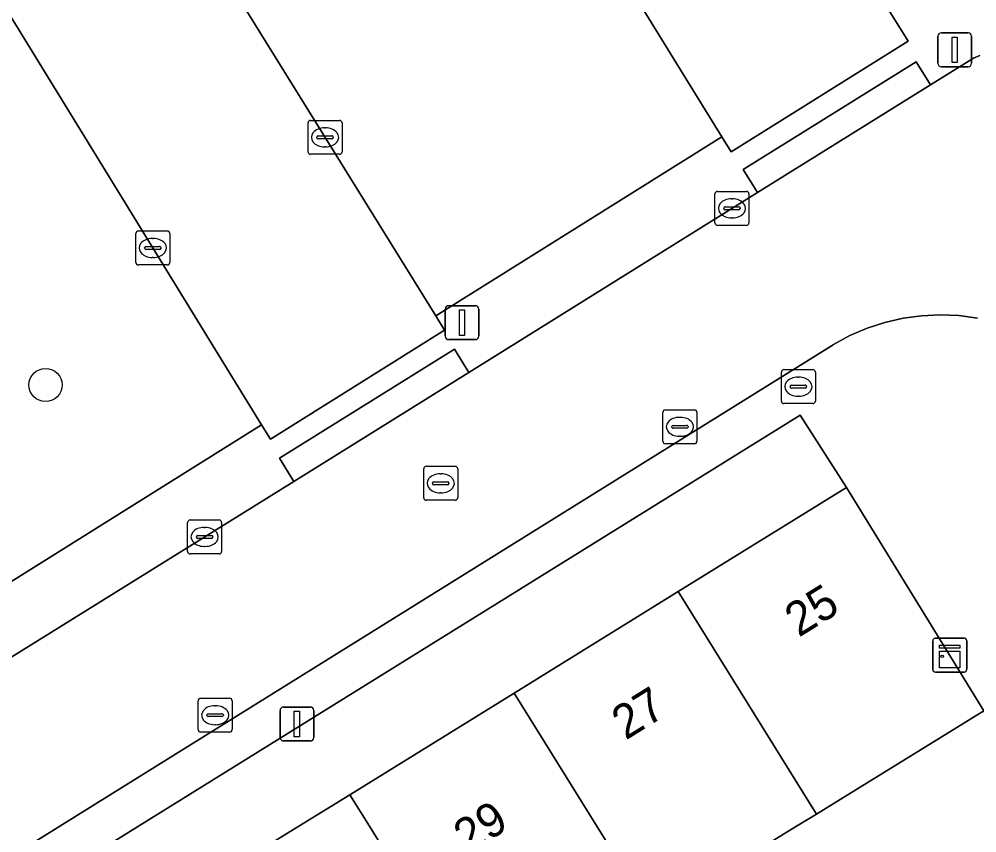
# Model space of a CAD drawing. Extents: x 160304 to 160955, y 383684 to 384161.
# Drawn here: x 160703.42 to 160731.63, y 383999.81 to 384023.78 of the extents above; entities that cross this region are included whole.
import ezdxf

# ---------------------------------------------------------------- set-up
doc = ezdxf.new("R2010")
doc.units = 0
for name, color, linetype in [('IMGEO_Boom', 7, 'Continuous'), ('IMGEO_Brandkraan', 7, 'Continuous'), ('IMGEO_Erf', 7, 'Continuous'), ('IMGEO_Kast', 7, 'Continuous'), ('IMGEO_Kolk', 7, 'Continuous'), ('IMGEO_Lichtmast', 7, 'Continuous'), ('IMGEO_Pand', 7, 'Continuous'), ('IMGEO_Pand_nummerreeks', 7, 'Continuous'), ('IMGEO_Parkeervlak_open', 7, 'Continuous'), ('IMGEO_Rijbaan_lokaal_open', 7, 'Continuous'), ('IMGEO_Rioolput', 7, 'Continuous'), ('IMGEO_Voetpad_open', 7, 'Continuous')]:
    doc.layers.add(name, color=color, linetype=linetype)

msp = doc.modelspace()

# ---------------------------------------------------------------- linework, layer by layer
at = {"layer": 'IMGEO_Boom'}
msp.add_circle((160704.196, 384013.001), 0.489, dxfattribs=at)
at = {"layer": 'IMGEO_Brandkraan'}
for p, q in [((160725.946, 384013.453), (160726.798, 384013.453)), ((160725.871, 384012.527), (160725.871, 384013.379)), ((160726.359, 384013.233), (160726.384, 384013.233)), ((160726.872, 384013.379), (160726.872, 384012.527)), ((160726.13, 384012.947), (160726.13, 384012.959)), ((160726.568, 384012.91), (160726.17, 384012.91)), ((160726.173, 384012.996), (160726.571, 384012.996)), ((160726.614, 384012.959), (160726.614, 384012.947)), ((160726.382, 384012.673), (160726.357, 384012.673)), ((160726.798, 384012.453), (160725.946, 384012.453))]:
    msp.add_line(p, q, dxfattribs=at)
for points in [[(160725.946, 384013.453), (160726.798, 384013.453)], [(160725.871, 384012.527), (160725.871, 384013.379)], [(160726.872, 384013.379), (160726.872, 384012.527)], [(160726.798, 384012.453), (160725.946, 384012.453)]]:
    msp.add_lwpolyline(points, dxfattribs=at)
for centre, radius, start, end in [((160725.948, 384013.377), 0.0765, 91.552, 178.448), ((160725.948, 384013.377), 0.0765, 91.552, 178.448), ((160726.796, 384013.377), 0.0765, 1.552, 88.448), ((160726.796, 384013.377), 0.0765, 1.552, 88.448), ((160726.17, 384012.956), 0.0403, 85.8775, 175.7526), ((160726.167, 384012.946), 0.0366, 178.938, 274.7102), ((160726.571, 384012.953), 0.043, 264.8664, 352.4533), ((160726.575, 384012.958), 0.0386, 1.7309, 96.639), ((160725.948, 384012.529), 0.0765, 181.552, 268.448), ((160725.948, 384012.529), 0.0765, 181.552, 268.448), ((160726.796, 384012.529), 0.0765, 271.552, 358.448), ((160726.796, 384012.529), 0.0765, 271.552, 358.448)]:
    msp.add_arc(centre, radius, start, end, dxfattribs=at)
for centre, major_axis, ratio, start_param, end_param in [((160726.358, 384012.953), (-0.387, 0.002), 0.722429, 4.712389, 7.853982), ((160726.383, 384012.953), (-0.39, 0.002), 0.717154, 1.570796, 4.712389)]:
    msp.add_ellipse(centre, major_axis=major_axis, ratio=ratio, start_param=start_param, end_param=end_param, dxfattribs=at)
at = {"layer": 'IMGEO_Erf'}
for points in [[(160708.32, 383997.939), (160711.652, 384000), (160713.157, 384000.931), (160717.995, 384003.923), (160722.832, 384006.915), (160727.787, 384009.979), (160726.422, 384012.115), (160706.936, 384000), (160687.05, 383987.636), (160676.351, 384000), (160656.955, 384022.413), (160655.424, 384021.087), (160659.239, 384016.681), (160662.975, 384012.366), (160666.712, 384008.05), (160670.447, 384003.736), (160673.681, 384000), (160674.183, 383999.42)], [(160736.358, 383996.235), (160733.983, 384000), (160731.839, 384003.398), (160727.6, 384000.788), (160726.904, 384000.36), (160726.32, 384000), (160722.061, 383997.377)]]:
    msp.add_lwpolyline(points, dxfattribs=at)
at = {"layer": 'IMGEO_Kast'}
for p, q in [((160730.404, 384005.542), (160731.245, 384005.542)), ((160731.245, 384005.542), (160730.404, 384005.542)), ((160730.329, 384004.617), (160730.329, 384005.458)), ((160730.329, 384005.458), (160730.329, 384004.617)), ((160731.329, 384005.467), (160731.329, 384004.626)), ((160731.329, 384004.626), (160731.329, 384005.467)), ((160731.254, 384004.542), (160730.413, 384004.542)), ((160730.413, 384004.542), (160731.254, 384004.542))]:
    msp.add_line(p, q, dxfattribs=at)
for points in [[(160730.524, 384005.332), (160731.124, 384005.332), (160731.124, 384005.247), (160730.524, 384005.247), (160730.524, 384005.332)], [(160730.524, 384005.157), (160731.124, 384005.157), (160731.124, 384004.668), (160730.524, 384004.668), (160730.524, 384005.157)]]:
    msp.add_lwpolyline(points, dxfattribs=at)
msp.add_circle((160730.608, 384005.006), 0.0377, dxfattribs=at)
for centre, start, end in [((160730.407, 384005.464), 92.4484, 184.2845), ((160730.407, 384005.464), 92.4484, 184.2845), ((160731.251, 384005.464), 2.4484, 94.2845), ((160731.251, 384005.464), 2.4484, 94.2845), ((160730.407, 384004.62), 182.4484, 274.2845), ((160730.407, 384004.62), 182.4484, 274.2845), ((160731.251, 384004.62), 272.4484, 4.2845), ((160731.251, 384004.62), 272.4484, 4.2845)]:
    msp.add_arc(centre, 0.0779, start, end, dxfattribs=at)
at = {"layer": 'IMGEO_Kolk'}
for p, q in [((160711.928, 384019.87), (160711.928, 384020.722)), ((160712.003, 384020.796), (160712.855, 384020.796)), ((160712.929, 384020.722), (160712.929, 384019.87)), ((160712.416, 384020.576), (160712.441, 384020.576)), ((160712.187, 384020.29), (160712.187, 384020.302)), ((160712.625, 384020.253), (160712.227, 384020.253)), ((160712.23, 384020.339), (160712.628, 384020.339)), ((160712.671, 384020.302), (160712.671, 384020.29)), ((160712.439, 384020.016), (160712.414, 384020.016)), ((160712.855, 384019.796), (160712.003, 384019.796)), ((160723.914, 384017.777), (160723.914, 384018.629)), ((160723.989, 384018.703), (160724.841, 384018.703)), ((160724.402, 384018.483), (160724.427, 384018.483)), ((160724.915, 384018.629), (160724.915, 384017.777)), ((160724.173, 384018.197), (160724.173, 384018.209)), ((160724.216, 384018.246), (160724.614, 384018.246)), ((160724.657, 384018.209), (160724.657, 384018.197)), ((160724.611, 384018.16), (160724.213, 384018.16)), ((160724.425, 384017.923), (160724.4, 384017.923)), ((160724.841, 384017.703), (160723.989, 384017.703)), ((160706.854, 384016.612), (160706.854, 384017.464)), ((160706.929, 384017.538), (160707.781, 384017.538)), ((160707.855, 384017.464), (160707.855, 384016.612)), ((160707.156, 384017.081), (160707.554, 384017.081)), ((160707.342, 384017.318), (160707.367, 384017.318)), ((160707.113, 384017.032), (160707.113, 384017.044)), ((160707.551, 384016.995), (160707.153, 384016.995)), ((160707.597, 384017.044), (160707.597, 384017.032)), ((160707.781, 384016.538), (160706.929, 384016.538)), ((160707.365, 384016.758), (160707.34, 384016.758)), ((160722.455, 384012.268), (160723.307, 384012.268)), ((160722.38, 384011.342), (160722.38, 384012.194)), ((160722.868, 384012.048), (160722.893, 384012.048)), ((160723.381, 384012.194), (160723.381, 384011.342)), ((160722.639, 384011.762), (160722.639, 384011.774)), ((160723.077, 384011.725), (160722.679, 384011.725)), ((160722.682, 384011.811), (160723.08, 384011.811)), ((160723.123, 384011.774), (160723.123, 384011.762)), ((160722.891, 384011.488), (160722.866, 384011.488)), ((160723.307, 384011.268), (160722.455, 384011.268)), ((160708.379, 384008.099), (160708.379, 384008.951)), ((160708.454, 384009.025), (160709.306, 384009.025)), ((160709.38, 384008.951), (160709.38, 384008.099)), ((160708.867, 384008.805), (160708.892, 384008.805)), ((160708.638, 384008.519), (160708.638, 384008.531)), ((160709.076, 384008.482), (160708.678, 384008.482)), ((160708.681, 384008.568), (160709.079, 384008.568)), ((160709.122, 384008.531), (160709.122, 384008.519)), ((160709.306, 384008.025), (160708.454, 384008.025)), ((160708.89, 384008.245), (160708.865, 384008.245)), ((160708.691, 384002.847), (160708.691, 384003.699)), ((160708.766, 384003.773), (160709.618, 384003.773)), ((160709.179, 384003.553), (160709.204, 384003.553)), ((160709.692, 384003.699), (160709.692, 384002.847)), ((160708.95, 384003.267), (160708.95, 384003.279)), ((160709.388, 384003.23), (160708.99, 384003.23)), ((160708.993, 384003.316), (160709.391, 384003.316)), ((160709.434, 384003.279), (160709.434, 384003.267)), ((160709.202, 384002.993), (160709.177, 384002.993)), ((160709.618, 384002.773), (160708.766, 384002.773))]:
    msp.add_line(p, q, dxfattribs=at)
for points in [[(160711.928, 384019.87), (160711.928, 384020.722)], [(160712.003, 384020.796), (160712.855, 384020.796)], [(160712.929, 384020.722), (160712.929, 384019.87)], [(160712.855, 384019.796), (160712.003, 384019.796)], [(160723.914, 384017.777), (160723.914, 384018.629)], [(160723.989, 384018.703), (160724.841, 384018.703)], [(160724.915, 384018.629), (160724.915, 384017.777)], [(160724.841, 384017.703), (160723.989, 384017.703)], [(160706.854, 384016.612), (160706.854, 384017.464)], [(160706.929, 384017.538), (160707.781, 384017.538)], [(160707.855, 384017.464), (160707.855, 384016.612)], [(160707.781, 384016.538), (160706.929, 384016.538)], [(160722.455, 384012.268), (160723.307, 384012.268)], [(160722.38, 384011.342), (160722.38, 384012.194)], [(160723.381, 384012.194), (160723.381, 384011.342)], [(160723.307, 384011.268), (160722.455, 384011.268)], [(160708.379, 384008.099), (160708.379, 384008.951)], [(160708.454, 384009.025), (160709.306, 384009.025)], [(160709.38, 384008.951), (160709.38, 384008.099)], [(160709.306, 384008.025), (160708.454, 384008.025)], [(160708.691, 384002.847), (160708.691, 384003.699)], [(160708.766, 384003.773), (160709.618, 384003.773)], [(160709.692, 384003.699), (160709.692, 384002.847)], [(160709.618, 384002.773), (160708.766, 384002.773)]]:
    msp.add_lwpolyline(points, dxfattribs=at)
for centre, radius, start, end in [((160712.005, 384020.72), 0.0765, 91.552, 178.448), ((160712.005, 384020.72), 0.0765, 91.552, 178.448), ((160712.853, 384020.72), 0.0765, 1.552, 88.448), ((160712.853, 384020.72), 0.0765, 1.552, 88.448), ((160712.227, 384020.299), 0.0403, 85.8775, 175.7526), ((160712.224, 384020.289), 0.0366, 178.938, 274.7102), ((160712.628, 384020.296), 0.043, 264.8664, 352.4533), ((160712.632, 384020.301), 0.0386, 1.7309, 96.639), ((160712.005, 384019.872), 0.0765, 181.552, 268.448), ((160712.005, 384019.872), 0.0765, 181.552, 268.448), ((160712.853, 384019.872), 0.0765, 271.552, 358.448), ((160712.853, 384019.872), 0.0765, 271.552, 358.448), ((160723.991, 384018.627), 0.0765, 91.552, 178.448), ((160723.991, 384018.627), 0.0765, 91.552, 178.448), ((160724.839, 384018.627), 0.0765, 1.552, 88.448), ((160724.839, 384018.627), 0.0765, 1.552, 88.448), ((160724.213, 384018.206), 0.0403, 85.8775, 175.7526), ((160724.21, 384018.196), 0.0366, 178.938, 274.7102), ((160724.614, 384018.203), 0.043, 264.8664, 352.4533), ((160724.618, 384018.208), 0.0386, 1.7309, 96.639), ((160723.991, 384017.779), 0.0765, 181.552, 268.448), ((160723.991, 384017.779), 0.0765, 181.552, 268.448), ((160724.839, 384017.779), 0.0765, 271.552, 358.448), ((160724.839, 384017.779), 0.0765, 271.552, 358.448), ((160706.931, 384017.462), 0.0765, 91.552, 178.448), ((160706.931, 384017.462), 0.0765, 91.552, 178.448), ((160707.779, 384017.462), 0.0765, 1.552, 88.448), ((160707.779, 384017.462), 0.0765, 1.552, 88.448), ((160707.153, 384017.041), 0.0403, 85.8775, 175.7526), ((160707.558, 384017.043), 0.0386, 1.7309, 96.639), ((160707.15, 384017.031), 0.0366, 178.938, 274.7102), ((160707.554, 384017.038), 0.043, 264.8664, 352.4533), ((160706.931, 384016.614), 0.0765, 181.552, 268.448), ((160706.931, 384016.614), 0.0765, 181.552, 268.448), ((160707.779, 384016.614), 0.0765, 271.552, 358.448), ((160707.779, 384016.614), 0.0765, 271.552, 358.448), ((160722.457, 384012.192), 0.0765, 91.552, 178.448), ((160722.457, 384012.192), 0.0765, 91.552, 178.448), ((160723.305, 384012.192), 0.0765, 1.552, 88.448), ((160723.305, 384012.192), 0.0765, 1.552, 88.448), ((160722.679, 384011.771), 0.0403, 85.8775, 175.7526), ((160722.676, 384011.761), 0.0366, 178.938, 274.7102), ((160723.08, 384011.768), 0.043, 264.8664, 352.4533), ((160723.084, 384011.773), 0.0386, 1.7309, 96.639), ((160722.457, 384011.344), 0.0765, 181.552, 268.448), ((160722.457, 384011.344), 0.0765, 181.552, 268.448), ((160723.305, 384011.344), 0.0765, 271.552, 358.448), ((160723.305, 384011.344), 0.0765, 271.552, 358.448), ((160708.456, 384008.949), 0.0765, 91.552, 178.448), ((160708.456, 384008.949), 0.0765, 91.552, 178.448), ((160709.304, 384008.949), 0.0765, 1.552, 88.448), ((160709.304, 384008.949), 0.0765, 1.552, 88.448), ((160708.678, 384008.528), 0.0403, 85.8775, 175.7526), ((160708.675, 384008.518), 0.0366, 178.938, 274.7102), ((160709.079, 384008.525), 0.043, 264.8664, 352.4533), ((160709.083, 384008.53), 0.0386, 1.7309, 96.639), ((160708.456, 384008.101), 0.0765, 181.552, 268.448), ((160708.456, 384008.101), 0.0765, 181.552, 268.448), ((160709.304, 384008.101), 0.0765, 271.552, 358.448), ((160709.304, 384008.101), 0.0765, 271.552, 358.448), ((160708.768, 384003.697), 0.0765, 91.552, 178.448), ((160708.768, 384003.697), 0.0765, 91.552, 178.448), ((160709.616, 384003.697), 0.0765, 1.552, 88.448), ((160709.616, 384003.697), 0.0765, 1.552, 88.448), ((160708.99, 384003.276), 0.0403, 85.8775, 175.7526), ((160708.987, 384003.266), 0.0366, 178.938, 274.7102), ((160709.391, 384003.273), 0.043, 264.8664, 352.4533), ((160709.395, 384003.278), 0.0386, 1.7309, 96.639), ((160708.768, 384002.849), 0.0765, 181.552, 268.448), ((160708.768, 384002.849), 0.0765, 181.552, 268.448), ((160709.616, 384002.849), 0.0765, 271.552, 358.448), ((160709.616, 384002.849), 0.0765, 271.552, 358.448)]:
    msp.add_arc(centre, radius, start, end, dxfattribs=at)
for centre, major_axis, ratio, start_param, end_param in [((160712.415, 384020.296), (-0.387, 0.002), 0.722429, 4.712389, 7.853982), ((160712.44, 384020.296), (-0.39, 0.002), 0.717154, 1.570796, 4.712389), ((160724.401, 384018.203), (-0.387, 0.002), 0.722429, 4.712389, 7.853982), ((160724.426, 384018.203), (-0.39, 0.002), 0.717154, 1.570796, 4.712389), ((160707.341, 384017.038), (-0.387, 0.002), 0.722429, 4.712389, 7.853982), ((160707.366, 384017.038), (-0.39, 0.002), 0.717154, 1.570796, 4.712389), ((160722.867, 384011.768), (-0.387, 0.002), 0.722429, 4.712389, 7.853982), ((160722.892, 384011.768), (-0.39, 0.002), 0.717154, 1.570796, 4.712389), ((160708.866, 384008.525), (-0.387, 0.002), 0.722429, 4.712389, 7.853982), ((160708.891, 384008.525), (-0.39, 0.002), 0.717154, 1.570796, 4.712389), ((160709.178, 384003.273), (-0.387, 0.002), 0.722429, 4.712389, 7.853982), ((160709.203, 384003.273), (-0.39, 0.002), 0.717154, 1.570796, 4.712389)]:
    msp.add_ellipse(centre, major_axis=major_axis, ratio=ratio, start_param=start_param, end_param=end_param, dxfattribs=at)
at = {"layer": 'IMGEO_Lichtmast'}
for p, q in [((160730.483, 384022.477), (160730.483, 384023.277)), ((160730.483, 384023.277), (160730.483, 384022.477)), ((160730.583, 384023.377), (160731.373, 384023.377)), ((160731.373, 384023.377), (160730.583, 384023.377)), ((160731.473, 384023.277), (160731.473, 384022.477)), ((160731.473, 384022.477), (160731.473, 384023.277)), ((160731.373, 384022.377), (160730.583, 384022.377)), ((160730.583, 384022.377), (160731.373, 384022.377)), ((160715.97, 384014.437), (160715.97, 384015.237)), ((160715.97, 384015.237), (160715.97, 384014.437)), ((160716.07, 384015.337), (160716.86, 384015.337)), ((160716.86, 384015.337), (160716.07, 384015.337)), ((160716.96, 384015.237), (160716.96, 384014.437)), ((160716.96, 384014.437), (160716.96, 384015.237)), ((160716.86, 384014.337), (160716.07, 384014.337)), ((160716.07, 384014.337), (160716.86, 384014.337)), ((160711.203, 384003.513), (160711.993, 384003.513)), ((160711.993, 384003.513), (160711.203, 384003.513)), ((160711.103, 384002.613), (160711.103, 384003.413)), ((160711.103, 384003.413), (160711.103, 384002.613)), ((160712.093, 384003.413), (160712.093, 384002.613)), ((160712.093, 384002.613), (160712.093, 384003.413)), ((160711.993, 384002.513), (160711.203, 384002.513)), ((160711.203, 384002.513), (160711.993, 384002.513))]:
    msp.add_line(p, q, dxfattribs=at)
for points in [[(160730.903, 384023.252), (160731.053, 384023.252), (160731.053, 384022.502), (160730.903, 384022.502), (160730.903, 384023.252)], [(160716.39, 384015.212), (160716.54, 384015.212), (160716.54, 384014.462), (160716.39, 384014.462), (160716.39, 384015.212)], [(160711.523, 384003.388), (160711.673, 384003.388), (160711.673, 384002.638), (160711.523, 384002.638), (160711.523, 384003.388)]]:
    msp.add_lwpolyline(points, dxfattribs=at)
for centre, start, end in [((160730.583, 384023.277), 90, 180), ((160730.583, 384023.277), 90, 180), ((160731.373, 384023.277), 0, 90), ((160731.373, 384023.277), 360, 90), ((160730.583, 384022.477), 180, 270), ((160730.583, 384022.477), 180, 270), ((160731.373, 384022.477), 270, 0), ((160731.373, 384022.477), 270, 0), ((160716.07, 384015.237), 90, 180), ((160716.07, 384015.237), 90, 180), ((160716.86, 384015.237), 0, 90), ((160716.86, 384015.237), 360, 90), ((160716.07, 384014.437), 180, 270), ((160716.07, 384014.437), 180, 270), ((160716.86, 384014.437), 270, 0), ((160716.86, 384014.437), 270, 0), ((160711.203, 384003.413), 90, 180), ((160711.203, 384003.413), 90, 180), ((160711.993, 384003.413), 0, 90), ((160711.993, 384003.413), 360, 90), ((160711.203, 384002.613), 180, 270), ((160711.203, 384002.613), 180, 270), ((160711.993, 384002.613), 270, 0), ((160711.993, 384002.613), 270, 0)]:
    msp.add_arc(centre, 0.1, start, end, dxfattribs=at)
at = {"layer": 'IMGEO_Pand'}
for points in [[(160726.904, 384000.36), (160727.6, 384000.788), (160731.839, 384003.398), (160727.787, 384009.979), (160722.832, 384006.915)], [(160717.995, 384003.923), (160720.432, 384000), (160722.061, 383997.377), (160726.32, 384000), (160726.904, 384000.36), (160722.832, 384006.915)], [(160717.995, 384003.923), (160713.157, 384000.931), (160713.735, 384000), (160717.217, 383994.395), (160722.061, 383997.377), (160720.432, 384000)], [(160717.217, 383994.395), (160713.735, 384000), (160713.157, 384000.931), (160711.652, 384000), (160708.32, 383997.939), (160712.375, 383991.412)]]:
    msp.add_lwpolyline(points, close=True, dxfattribs=at)
at = {"layer": 'IMGEO_Parkeervlak_open'}
for points in [[(160715.687, 384015.035), (160724.118, 384020.31), (160715.343, 384034.554), (160706.863, 384029.281)], [(160701.775, 384026.118), (160699.065, 384024.433), (160698.807, 384024.272), (160699.178, 384023.678), (160693.718, 384020.269), (160702.191, 384006.592), (160710.558, 384011.827)]]:
    msp.add_lwpolyline(points, close=True, dxfattribs=at)
at = {"layer": 'IMGEO_Rijbaan_lokaal_open'}
for points in [[(160724.118, 384020.31), (160724.39, 384019.868), (160729.607, 384023.129), (160726.672, 384027.846), (160723.086, 384033.617), (160720.51, 384037.766), (160715.343, 384034.554)], [(160710.558, 384011.827), (160710.817, 384011.406), (160715.944, 384014.62), (160715.687, 384015.035), (160706.863, 384029.281), (160701.775, 384026.118)]]:
    msp.add_lwpolyline(points, close=True, dxfattribs=at)
for points in [[(160731.717, 384022.712), (160731.529, 384022.633), (160730.264, 384021.845), (160725.171, 384018.672), (160716.664, 384013.373), (160711.511, 384010.162), (160703.128, 384004.94)], [(160698.705, 383996.323), (160704.611, 384000), (160727.392, 384014.184), (160727.407, 384014.193), (160727.891, 384014.455), (160728.396, 384014.672), (160728.919, 384014.843), (160729.454, 384014.967), (160729.999, 384015.042), (160730.548, 384015.069), (160731.098, 384015.046), (160731.643, 384014.974)]]:
    msp.add_lwpolyline(points, dxfattribs=at)
at = {"layer": 'IMGEO_Rioolput'}
for p, q in [((160715.41, 384010.605), (160716.262, 384010.605)), ((160715.335, 384009.679), (160715.335, 384010.531)), ((160715.823, 384010.385), (160715.848, 384010.385)), ((160716.336, 384010.531), (160716.336, 384009.679)), ((160715.594, 384010.099), (160715.594, 384010.111)), ((160716.032, 384010.062), (160715.634, 384010.062)), ((160715.637, 384010.148), (160716.035, 384010.148)), ((160716.078, 384010.111), (160716.078, 384010.099)), ((160715.846, 384009.825), (160715.821, 384009.825)), ((160716.262, 384009.605), (160715.41, 384009.605))]:
    msp.add_line(p, q, dxfattribs=at)
for points in [[(160715.41, 384010.605), (160716.262, 384010.605)], [(160715.335, 384009.679), (160715.335, 384010.531)], [(160716.336, 384010.531), (160716.336, 384009.679)], [(160716.262, 384009.605), (160715.41, 384009.605)]]:
    msp.add_lwpolyline(points, dxfattribs=at)
for centre, radius, start, end in [((160715.412, 384010.529), 0.0765, 91.552, 178.448), ((160715.412, 384010.529), 0.0765, 91.552, 178.448), ((160716.26, 384010.529), 0.0765, 1.552, 88.448), ((160716.26, 384010.529), 0.0765, 1.552, 88.448), ((160715.634, 384010.108), 0.0403, 85.8775, 175.7526), ((160715.631, 384010.098), 0.0366, 178.938, 274.7102), ((160716.035, 384010.105), 0.043, 264.8664, 352.4533), ((160716.039, 384010.11), 0.0386, 1.7309, 96.639), ((160715.412, 384009.681), 0.0765, 181.552, 268.448), ((160715.412, 384009.681), 0.0765, 181.552, 268.448), ((160716.26, 384009.681), 0.0765, 271.552, 358.448), ((160716.26, 384009.681), 0.0765, 271.552, 358.448)]:
    msp.add_arc(centre, radius, start, end, dxfattribs=at)
for centre, major_axis, ratio, start_param, end_param in [((160715.822, 384010.105), (-0.387, 0.002), 0.722429, 4.712389, 7.853982), ((160715.847, 384010.105), (-0.39, 0.002), 0.717154, 1.570796, 4.712389)]:
    msp.add_ellipse(centre, major_axis=major_axis, ratio=ratio, start_param=start_param, end_param=end_param, dxfattribs=at)
at = {"layer": 'IMGEO_Voetpad_open'}
for points in [[(160725.711, 384040.981), (160720.51, 384037.766), (160723.086, 384033.617), (160723.995, 384034.182), (160727.579, 384028.415), (160726.672, 384027.846), (160729.607, 384023.129), (160724.39, 384019.868), (160724.118, 384020.31), (160715.687, 384015.035), (160715.944, 384014.62), (160710.817, 384011.406), (160710.558, 384011.827), (160702.191, 384006.592)], [(160703.128, 384004.94), (160711.511, 384010.162), (160711.088, 384010.841), (160716.24, 384014.052), (160716.664, 384013.373), (160725.171, 384018.672), (160724.748, 384019.352), (160729.841, 384022.525), (160730.264, 384021.845), (160731.529, 384022.633), (160731.717, 384022.712)], [(160731.643, 384014.974), (160731.098, 384015.046), (160730.548, 384015.069), (160729.999, 384015.042), (160729.454, 384014.967), (160728.919, 384014.843), (160728.396, 384014.672), (160727.891, 384014.455), (160727.407, 384014.193), (160727.392, 384014.184), (160704.611, 384000), (160698.705, 383996.323)], [(160687.05, 383987.636), (160706.936, 384000), (160726.422, 384012.115), (160727.787, 384009.979), (160731.839, 384003.398), (160733.983, 384000), (160736.358, 383996.235)]]:
    msp.add_lwpolyline(points, dxfattribs=at)
for points in [[(160725.171, 384018.672), (160730.264, 384021.845), (160729.841, 384022.525), (160724.748, 384019.352)], [(160711.511, 384010.162), (160716.664, 384013.373), (160716.24, 384014.052), (160711.088, 384010.841)]]:
    msp.add_lwpolyline(points, close=True, dxfattribs=at)

# ---------------------------------------------------------------- texts
at = {"layer": 'IMGEO_Pand_nummerreeks'}
for s, rotation, p in [('25', 31.8921, (160726.384, 384005.552)), ('27', 31.8921, (160721.285, 384002.523)), ('29', 31.9018, (160716.629, 383999.173))]:
    msp.add_text(s, height=1, rotation=rotation, dxfattribs=at).set_placement(p)

doc.saveas('drawing.dxf')
